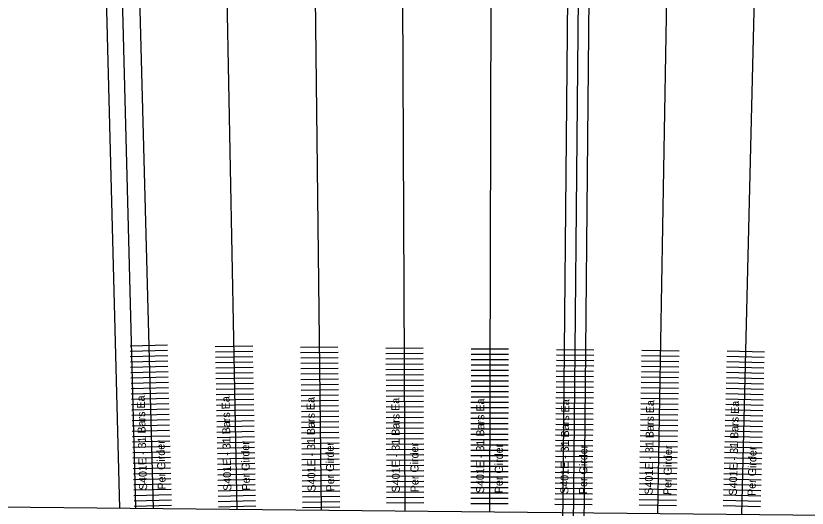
# Model space of a CAD drawing. Extents: x 632276 to 635000, y 381313 to 381846.
# Drawn here: x 634781.2 to 634855.3, y 381401 to 381447.2 of the extents above; entities that cross this region are included whole.
import ezdxf

# ---------------------------------------------------------------- set-up
doc = ezdxf.new("R2010")
doc.units = 0
for name, color, linetype in [('B_Boring Annot', 7, 'Continuous'), ('B_No_Plot', 7, 'Continuous'), ('R_Border_Scale', 7, 'Continuous'), ('R_Road Edge of Shoulder', 7, 'Continuous'), ('R_Shade Removal', 7, 'Continuous'), ('R_Wall', 7, 'Continuous')]:
    doc.layers.add(name, color=color, linetype=linetype)

msp = doc.modelspace()

# ---------------------------------------------------------------- linework, layer by layer
at = {"layer": 'B_Boring Annot'}
for p, q in [((634832.38, 381395.621), (634835.411, 381700.486)), ((634834.38, 381395.601), (634837.411, 381700.466)), ((634785.119, 381621.102), (634790.932, 381401.034)), ((634786.619, 381621.142), (634792.431, 381401.073))]:
    msp.add_line(p, q, dxfattribs=at)
at = {"layer": 'B_No_Plot'}
msp.add_line((634669.11, 381402.245), (634997.749, 381398.977), dxfattribs=at)
at = {"layer": 'R_Border_Scale'}
for p, q in [((634795.403, 381416.293), (634791.904, 381416.201)), ((634803.388, 381416.205), (634799.889, 381416.138)), ((634795.416, 381415.794), (634791.917, 381415.701)), ((634803.398, 381415.705), (634799.898, 381415.638)), ((634811.374, 381416.116), (634807.874, 381416.074)), ((634811.38, 381415.616), (634807.88, 381415.574)), ((634819.359, 381416.026), (634815.859, 381416.009)), ((634819.362, 381415.526), (634815.862, 381415.509)), ((634827.345, 381415.935), (634823.845, 381415.944)), ((634835.333, 381415.843), (634831.833, 381415.878)), ((634843.317, 381415.75), (634839.818, 381415.811)), ((634851.302, 381415.657), (634847.803, 381415.743)), ((634795.429, 381415.294), (634791.93, 381415.201)), ((634795.442, 381414.794), (634791.943, 381414.702)), ((634803.407, 381415.205), (634799.908, 381415.138)), ((634811.386, 381415.116), (634807.886, 381415.074)), ((634819.364, 381415.026), (634815.864, 381415.009)), ((634827.342, 381414.935), (634823.842, 381414.944)), ((634827.343, 381415.435), (634823.843, 381415.444)), ((634835.323, 381414.843), (634831.823, 381414.878)), ((634835.328, 381415.343), (634831.828, 381415.378)), ((634843.3, 381414.75), (634839.8, 381414.811)), ((634843.309, 381415.25), (634839.809, 381415.311)), ((634851.278, 381414.657), (634847.779, 381414.743)), ((634851.29, 381415.157), (634847.791, 381415.243)), ((634795.455, 381414.294), (634791.957, 381414.202)), ((634803.417, 381414.705), (634799.918, 381414.638)), ((634803.427, 381414.205), (634799.927, 381414.138)), ((634811.392, 381414.616), (634807.892, 381414.574)), ((634811.398, 381414.116), (634807.898, 381414.074)), ((634819.366, 381414.526), (634815.866, 381414.509)), ((634819.369, 381414.026), (634815.869, 381414.009)), ((634827.341, 381414.435), (634823.841, 381414.444)), ((634835.318, 381414.343), (634831.818, 381414.378)), ((634843.291, 381414.25), (634839.792, 381414.311)), ((634851.265, 381414.157), (634847.766, 381414.243)), ((634795.469, 381413.794), (634791.97, 381413.702)), ((634795.482, 381413.294), (634791.983, 381413.202)), ((634803.436, 381413.705), (634799.937, 381413.638)), ((634811.403, 381413.616), (634807.904, 381413.574)), ((634819.371, 381413.526), (634815.871, 381413.509)), ((634827.338, 381413.435), (634823.838, 381413.444)), ((634827.339, 381413.935), (634823.839, 381413.944)), ((634835.308, 381413.343), (634831.808, 381413.378)), ((634835.313, 381413.843), (634831.813, 381413.878)), ((634843.274, 381413.251), (634839.774, 381413.311)), ((634843.283, 381413.75), (634839.783, 381413.811)), ((634851.241, 381413.158), (634847.742, 381413.244)), ((634851.253, 381413.657), (634847.754, 381413.743)), ((634795.495, 381412.795), (634791.996, 381412.702)), ((634803.446, 381413.205), (634799.946, 381413.138)), ((634803.455, 381412.706), (634799.956, 381412.639)), ((634811.409, 381413.116), (634807.91, 381413.074)), ((634811.415, 381412.616), (634807.916, 381412.574)), ((634819.373, 381413.026), (634815.873, 381413.009)), ((634819.375, 381412.526), (634815.875, 381412.509)), ((634827.337, 381412.935), (634823.837, 381412.944)), ((634835.303, 381412.843), (634831.803, 381412.878)), ((634843.265, 381412.751), (634839.766, 381412.811)), ((634851.229, 381412.658), (634847.73, 381412.744)), ((634795.508, 381412.295), (634792.009, 381412.202)), ((634795.521, 381411.795), (634792.023, 381411.703)), ((634803.465, 381412.206), (634799.965, 381412.139)), ((634811.421, 381412.116), (634807.922, 381412.074)), ((634819.378, 381412.026), (634815.878, 381412.009)), ((634827.334, 381411.935), (634823.834, 381411.944)), ((634827.335, 381412.435), (634823.835, 381412.444)), ((634835.293, 381411.843), (634831.793, 381411.878)), ((634835.298, 381412.343), (634831.798, 381412.378)), ((634843.248, 381411.751), (634839.748, 381411.811)), ((634843.257, 381412.251), (634839.757, 381412.311)), ((634851.216, 381412.158), (634847.717, 381412.244)), ((634795.535, 381411.295), (634792.036, 381411.203)), ((634803.474, 381411.706), (634799.975, 381411.639)), ((634803.484, 381411.206), (634799.985, 381411.139)), ((634811.427, 381411.616), (634807.927, 381411.574)), ((634811.433, 381411.116), (634807.933, 381411.074)), ((634819.38, 381411.526), (634815.88, 381411.509)), ((634819.382, 381411.026), (634815.882, 381411.009)), ((634827.333, 381411.435), (634823.833, 381411.444)), ((634835.288, 381411.343), (634831.788, 381411.378)), ((634843.239, 381411.251), (634839.74, 381411.311)), ((634851.192, 381411.158), (634847.693, 381411.244)), ((634851.204, 381411.658), (634847.705, 381411.744)), ((634795.548, 381410.795), (634792.049, 381410.703)), ((634795.561, 381410.295), (634792.062, 381410.203)), ((634803.494, 381410.706), (634799.994, 381410.639)), ((634811.439, 381410.616), (634807.939, 381410.574)), ((634819.385, 381410.526), (634815.885, 381410.509)), ((634827.33, 381410.435), (634823.83, 381410.444)), ((634827.331, 381410.935), (634823.831, 381410.944)), ((634835.277, 381410.343), (634831.778, 381410.378)), ((634835.283, 381410.843), (634831.783, 381410.878)), ((634843.222, 381410.251), (634839.723, 381410.312)), ((634843.231, 381410.751), (634839.731, 381410.812)), ((634851.179, 381410.658), (634847.68, 381410.744)), ((634795.574, 381409.796), (634792.075, 381409.703)), ((634803.503, 381410.206), (634800.004, 381410.139)), ((634803.513, 381409.706), (634800.013, 381409.639)), ((634811.445, 381410.116), (634807.945, 381410.074)), ((634811.451, 381409.616), (634807.951, 381409.575)), ((634819.387, 381410.026), (634815.887, 381410.009)), ((634819.389, 381409.526), (634815.889, 381409.509)), ((634827.329, 381409.935), (634823.829, 381409.944)), ((634835.272, 381409.843), (634831.773, 381409.878)), ((634843.213, 381409.751), (634839.714, 381409.812)), ((634851.155, 381409.659), (634847.656, 381409.745)), ((634851.167, 381410.159), (634847.668, 381410.245)), ((634795.587, 381409.296), (634792.089, 381409.203)), ((634795.601, 381408.796), (634792.102, 381408.704)), ((634803.522, 381409.206), (634800.023, 381409.139)), ((634811.457, 381409.116), (634807.957, 381409.075)), ((634819.392, 381409.026), (634815.892, 381409.009)), ((634827.326, 381408.935), (634823.826, 381408.944)), ((634827.327, 381409.435), (634823.828, 381409.444)), ((634835.262, 381408.843), (634831.762, 381408.878)), ((634835.267, 381409.343), (634831.768, 381409.378)), ((634843.196, 381408.751), (634839.697, 381408.812)), ((634843.205, 381409.251), (634839.705, 381409.312)), ((634851.143, 381409.159), (634847.644, 381409.245)), ((634795.614, 381408.296), (634792.115, 381408.204)), ((634803.532, 381408.706), (634800.032, 381408.639)), ((634803.541, 381408.206), (634800.042, 381408.139)), ((634811.463, 381408.616), (634807.963, 381408.575)), ((634811.469, 381408.116), (634807.969, 381408.075)), ((634819.394, 381408.526), (634815.894, 381408.509)), ((634827.325, 381408.435), (634823.825, 381408.444)), ((634835.257, 381408.343), (634831.757, 381408.378)), ((634843.187, 381408.251), (634839.688, 381408.312)), ((634851.118, 381408.159), (634847.619, 381408.245)), ((634851.13, 381408.659), (634847.631, 381408.745)), ((634795.627, 381407.796), (634792.128, 381407.704)), ((634803.551, 381407.706), (634800.052, 381407.639)), ((634811.475, 381407.616), (634807.975, 381407.575)), ((634819.396, 381408.026), (634815.896, 381408.009)), ((634819.399, 381407.526), (634815.899, 381407.509)), ((634827.322, 381407.435), (634823.822, 381407.444)), ((634827.324, 381407.935), (634823.824, 381407.944)), ((634835.247, 381407.343), (634831.747, 381407.378)), ((634835.252, 381407.843), (634831.752, 381407.878)), ((634843.17, 381407.251), (634839.671, 381407.312)), ((634843.179, 381407.751), (634839.679, 381407.812)), ((634851.106, 381407.659), (634847.607, 381407.745)), ((634795.64, 381407.297), (634792.141, 381407.204)), ((634795.653, 381406.797), (634792.155, 381406.704)), ((634803.561, 381407.207), (634800.061, 381407.14)), ((634803.57, 381406.707), (634800.071, 381406.64)), ((634811.481, 381407.116), (634807.981, 381407.075)), ((634811.487, 381406.616), (634807.987, 381406.575)), ((634819.401, 381407.026), (634815.901, 381407.009)), ((634827.321, 381406.935), (634823.821, 381406.944)), ((634835.242, 381406.843), (634831.742, 381406.878)), ((634843.161, 381406.752), (634839.662, 381406.812)), ((634851.081, 381406.66), (634847.582, 381406.746)), ((634851.093, 381407.159), (634847.595, 381407.245)), ((634795.667, 381406.297), (634792.168, 381406.204)), ((634803.58, 381406.207), (634800.08, 381406.14)), ((634811.493, 381406.116), (634807.993, 381406.075)), ((634819.403, 381406.526), (634815.903, 381406.51)), ((634819.405, 381406.026), (634815.905, 381406.01)), ((634827.318, 381405.935), (634823.818, 381405.944)), ((634827.32, 381406.435), (634823.82, 381406.444)), ((634835.232, 381405.843), (634831.732, 381405.878)), ((634835.237, 381406.343), (634831.737, 381406.378)), ((634843.153, 381406.252), (634839.653, 381406.312)), ((634851.069, 381406.16), (634847.57, 381406.246)), ((634795.68, 381405.797), (634792.181, 381405.705)), ((634795.693, 381405.297), (634792.194, 381405.205)), ((634803.589, 381405.707), (634800.09, 381405.64)), ((634803.599, 381405.207), (634800.099, 381405.14)), ((634811.499, 381405.616), (634807.999, 381405.575)), ((634811.504, 381405.116), (634808.005, 381405.075)), ((634819.408, 381405.526), (634815.908, 381405.51)), ((634827.317, 381405.435), (634823.817, 381405.444)), ((634835.227, 381405.343), (634831.727, 381405.379)), ((634843.135, 381405.252), (634839.636, 381405.312)), ((634843.144, 381405.752), (634839.645, 381405.812)), ((634851.044, 381405.16), (634847.545, 381405.246)), ((634851.057, 381405.66), (634847.558, 381405.746)), ((634795.706, 381404.797), (634792.207, 381404.705)), ((634803.608, 381404.707), (634800.109, 381404.64)), ((634811.51, 381404.616), (634808.011, 381404.575)), ((634819.41, 381405.026), (634815.91, 381405.01)), ((634819.412, 381404.526), (634815.912, 381404.51)), ((634827.314, 381404.435), (634823.814, 381404.444)), ((634827.316, 381404.935), (634823.816, 381404.944)), ((634835.217, 381404.343), (634831.717, 381404.379)), ((634835.222, 381404.843), (634831.722, 381404.879)), ((634843.127, 381404.752), (634839.627, 381404.812)), ((634851.032, 381404.66), (634847.533, 381404.746)), ((634795.719, 381404.298), (634792.221, 381404.205)), ((634795.733, 381403.798), (634792.234, 381403.705)), ((634803.618, 381404.207), (634800.119, 381404.14)), ((634803.627, 381403.707), (634800.128, 381403.64)), ((634811.516, 381404.116), (634808.017, 381404.075)), ((634811.522, 381403.617), (634808.023, 381403.575)), ((634819.415, 381404.026), (634815.915, 381404.01)), ((634827.313, 381403.935), (634823.813, 381403.944)), ((634835.212, 381403.843), (634831.712, 381403.879)), ((634843.11, 381403.752), (634839.61, 381403.813)), ((634843.118, 381404.252), (634839.619, 381404.312)), ((634851.007, 381403.66), (634847.509, 381403.746)), ((634851.02, 381404.16), (634847.521, 381404.246)), ((634795.746, 381403.298), (634792.247, 381403.206)), ((634803.637, 381403.207), (634800.138, 381403.14)), ((634811.528, 381403.117), (634808.028, 381403.075)), ((634819.417, 381403.526), (634815.917, 381403.51)), ((634819.419, 381403.026), (634815.919, 381403.01)), ((634827.31, 381402.935), (634823.81, 381402.944)), ((634827.312, 381403.435), (634823.812, 381403.444)), ((634835.202, 381402.843), (634831.702, 381402.879)), ((634835.207, 381403.343), (634831.707, 381403.379)), ((634843.101, 381403.252), (634839.601, 381403.313)), ((634850.995, 381403.161), (634847.496, 381403.247)), ((634795.759, 381402.798), (634792.26, 381402.706)), ((634795.772, 381402.298), (634792.273, 381402.206)), ((634803.647, 381402.707), (634800.147, 381402.64)), ((634803.656, 381402.207), (634800.157, 381402.14)), ((634811.534, 381402.617), (634808.034, 381402.575)), ((634811.54, 381402.117), (634808.04, 381402.075)), ((634819.422, 381402.526), (634815.922, 381402.51)), ((634827.309, 381402.435), (634823.809, 381402.444)), ((634835.197, 381402.343), (634831.697, 381402.379)), ((634843.084, 381402.252), (634839.584, 381402.313)), ((634843.092, 381402.752), (634839.593, 381402.813)), ((634850.971, 381402.161), (634847.472, 381402.247)), ((634850.983, 381402.661), (634847.484, 381402.747)), ((634795.785, 381401.798), (634792.287, 381401.706)), ((634803.666, 381401.708), (634800.166, 381401.641)), ((634811.546, 381401.617), (634808.046, 381401.575)), ((634819.424, 381402.026), (634815.924, 381402.01)), ((634819.426, 381401.526), (634815.926, 381401.51)), ((634827.306, 381401.435), (634823.806, 381401.444)), ((634827.308, 381401.935), (634823.808, 381401.944)), ((634835.186, 381401.343), (634831.687, 381401.379)), ((634835.191, 381401.843), (634831.692, 381401.879)), ((634843.075, 381401.752), (634839.575, 381401.813)), ((634850.958, 381401.661), (634847.459, 381401.747)), ((634795.799, 381401.299), (634792.3, 381401.206)), ((634803.675, 381401.208), (634800.176, 381401.141)), ((634811.552, 381401.117), (634808.052, 381401.075)), ((634843.066, 381401.252), (634839.567, 381401.313)), ((634850.946, 381401.161), (634847.447, 381401.247))]:
    msp.add_line(p, q, dxfattribs=at)
at = {"layer": 'R_Road Edge of Shoulder'}
msp.add_line((634833.143, 381371.836), (634836.411, 381700.476), dxfattribs=at)
at = {"layer": 'R_Shade Removal'}
for p, q in [((634788.244, 381621.071), (634794.056, 381401.003)), ((634801.93, 381400.924), (634797.718, 381620.977)), ((634807.191, 381620.883), (634809.805, 381400.846)), ((634817.68, 381400.768), (634816.665, 381620.789)), ((634826.138, 381620.694), (634825.554, 381400.689)), ((634845.095, 381620.506), (634841.305, 381400.533)), ((634849.179, 381400.454), (634854.569, 381620.412))]:
    msp.add_line(p, q, dxfattribs=at)

# ---------------------------------------------------------------- texts
at = {"layer": 'R_Wall'}
for s, rotation, p in [('S401E - 31 Bars Ea,', 91.52278, (634793.51, 381402.739)), ('S401E - 31 Bars Ea,', 91.10681, (634801.397, 381402.664)), ('S401E - 31 Bars Ea,', 90.69065, (634809.284, 381402.59)), ('S401E - 31 Bars Ea,', 90.27437, (634817.172, 381402.515)), ('S401E - 31 Bars Ea,', 89.85799, (634825.059, 381402.441)), ('S401E - 31 Bars Ea,', 89.43036, (634832.947, 381402.366)), ('S401E - 31 Bars Ea,', 89.01848, (634840.834, 381402.291)), ('S401E - 31 Bars Ea,', 88.60208, (634848.721, 381402.216)), ('Per Girder', 91.52278, (634795.259, 381402.785)), ('Per Girder', 91.10681, (634803.147, 381402.698)), ('Per Girder', 90.69065, (634811.034, 381402.611)), ('Per Girder', 90.27437, (634818.922, 381402.524)), ('Per Girder', 89.85799, (634826.809, 381402.436)), ('Per Girder', 89.43036, (634834.697, 381402.349)), ('Per Girder', 89.01848, (634842.584, 381402.261)), ('Per Girder', 88.60208, (634850.471, 381402.173))]:
    msp.add_text(s, height=0.75, rotation=rotation, dxfattribs=at).set_placement(p)

doc.saveas('drawing.dxf')
